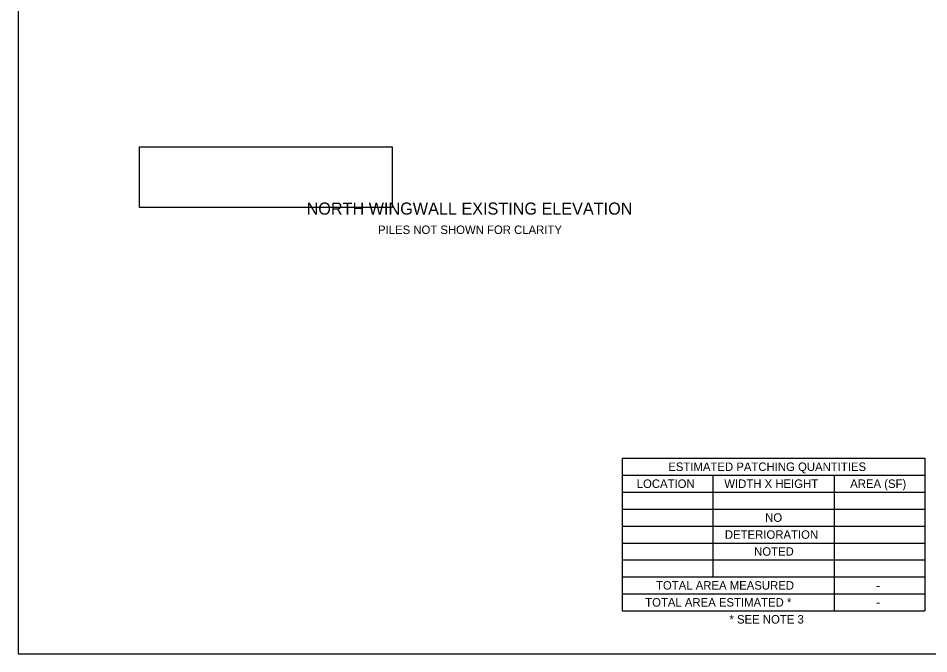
# Model space of a CAD drawing. Extents: x 100 to 130.5, y 100 to 121.
# Drawn here: x 100 to 115.03, y 100 to 110.5 of the extents above; entities that cross this region are included whole.
import ezdxf

# ---------------------------------------------------------------- set-up
doc = ezdxf.new("R2010")
doc.units = 0
for name, color, linetype in [('BR_P_Gen_Text', 7, 'Continuous'), ('SC_Scratch1', 7, 'Continuous'), ('SH_Masking', 7, 'Continuous')]:
    doc.layers.add(name, color=color, linetype=linetype)

msp = doc.modelspace()

# ---------------------------------------------------------------- linework, layer by layer
at = {"layer": 'BR_P_Gen_Text'}
for p, q in [((109.97, 103.23), (109.97, 100.71)), ((109.97, 103.23), (114.97, 103.23)), ((114.97, 103.23), (114.97, 100.71)), ((109.97, 102.95), (114.97, 102.95)), ((111.47, 102.95), (111.47, 101.27)), ((113.47, 102.95), (113.47, 100.71)), ((109.97, 102.67), (114.97, 102.67)), ((109.97, 102.39), (114.97, 102.39)), ((109.97, 102.11), (114.97, 102.11)), ((109.97, 101.83), (114.97, 101.83)), ((109.97, 101.55), (114.97, 101.55)), ((109.97, 101.27), (114.97, 101.27)), ((109.97, 100.99), (114.97, 100.99)), ((109.97, 100.71), (114.97, 100.71))]:
    msp.add_line(p, q, dxfattribs=at)
at = {"layer": 'SC_Scratch1'}
msp.add_lwpolyline([(100, 100), (130.5, 100), (130.5, 121), (100, 121)], close=True, dxfattribs=at)
at = {"layer": 'SH_Masking'}
msp.add_lwpolyline([(102.004, 108.374), (106.175, 108.374), (106.175, 107.373), (102.004, 107.373)], close=True, dxfattribs=at)

# ---------------------------------------------------------------- texts
at = {"layer": 'BR_P_Gen_Text'}
for s, height, p in [('NORTH WINGWALL EXISTING ELEVATION', 0.2, (104.762, 107.255)), ('PILES NOT SHOWN FOR CLARITY', 0.14, (105.941, 106.935)), ('ESTIMATED PATCHING QUANTITIES', 0.14, (110.733, 103.02)), ('LOCATION', 0.14, (110.212, 102.74)), ('WIDTH X HEIGHT', 0.14, (111.658, 102.74)), ('AREA (SF)', 0.14, (113.737, 102.74)), ('NO', 0.14, (112.333, 102.18)), ('DETERIORATION', 0.14, (111.668, 101.9)), ('NOTED', 0.14, (112.15, 101.62)), ('TOTAL AREA MEASURED', 0.14, (110.531, 101.06)), ('-', 0.14, (114.167, 101.06)), ('TOTAL AREA ESTIMATED *', 0.14, (110.352, 100.78)), ('-', 0.14, (114.167, 100.78)), ('* SEE NOTE 3', 0.14, (111.743, 100.5))]:
    msp.add_text(s, height=height, dxfattribs=at).set_placement(p)

doc.saveas('drawing.dxf')
